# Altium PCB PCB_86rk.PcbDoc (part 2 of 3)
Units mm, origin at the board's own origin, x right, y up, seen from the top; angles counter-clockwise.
Board outline 185 x 150 mm, 2 copper layers (Top Layer, Bottom Layer); 95 components, 233 nets, 810 pads, 336 vias.
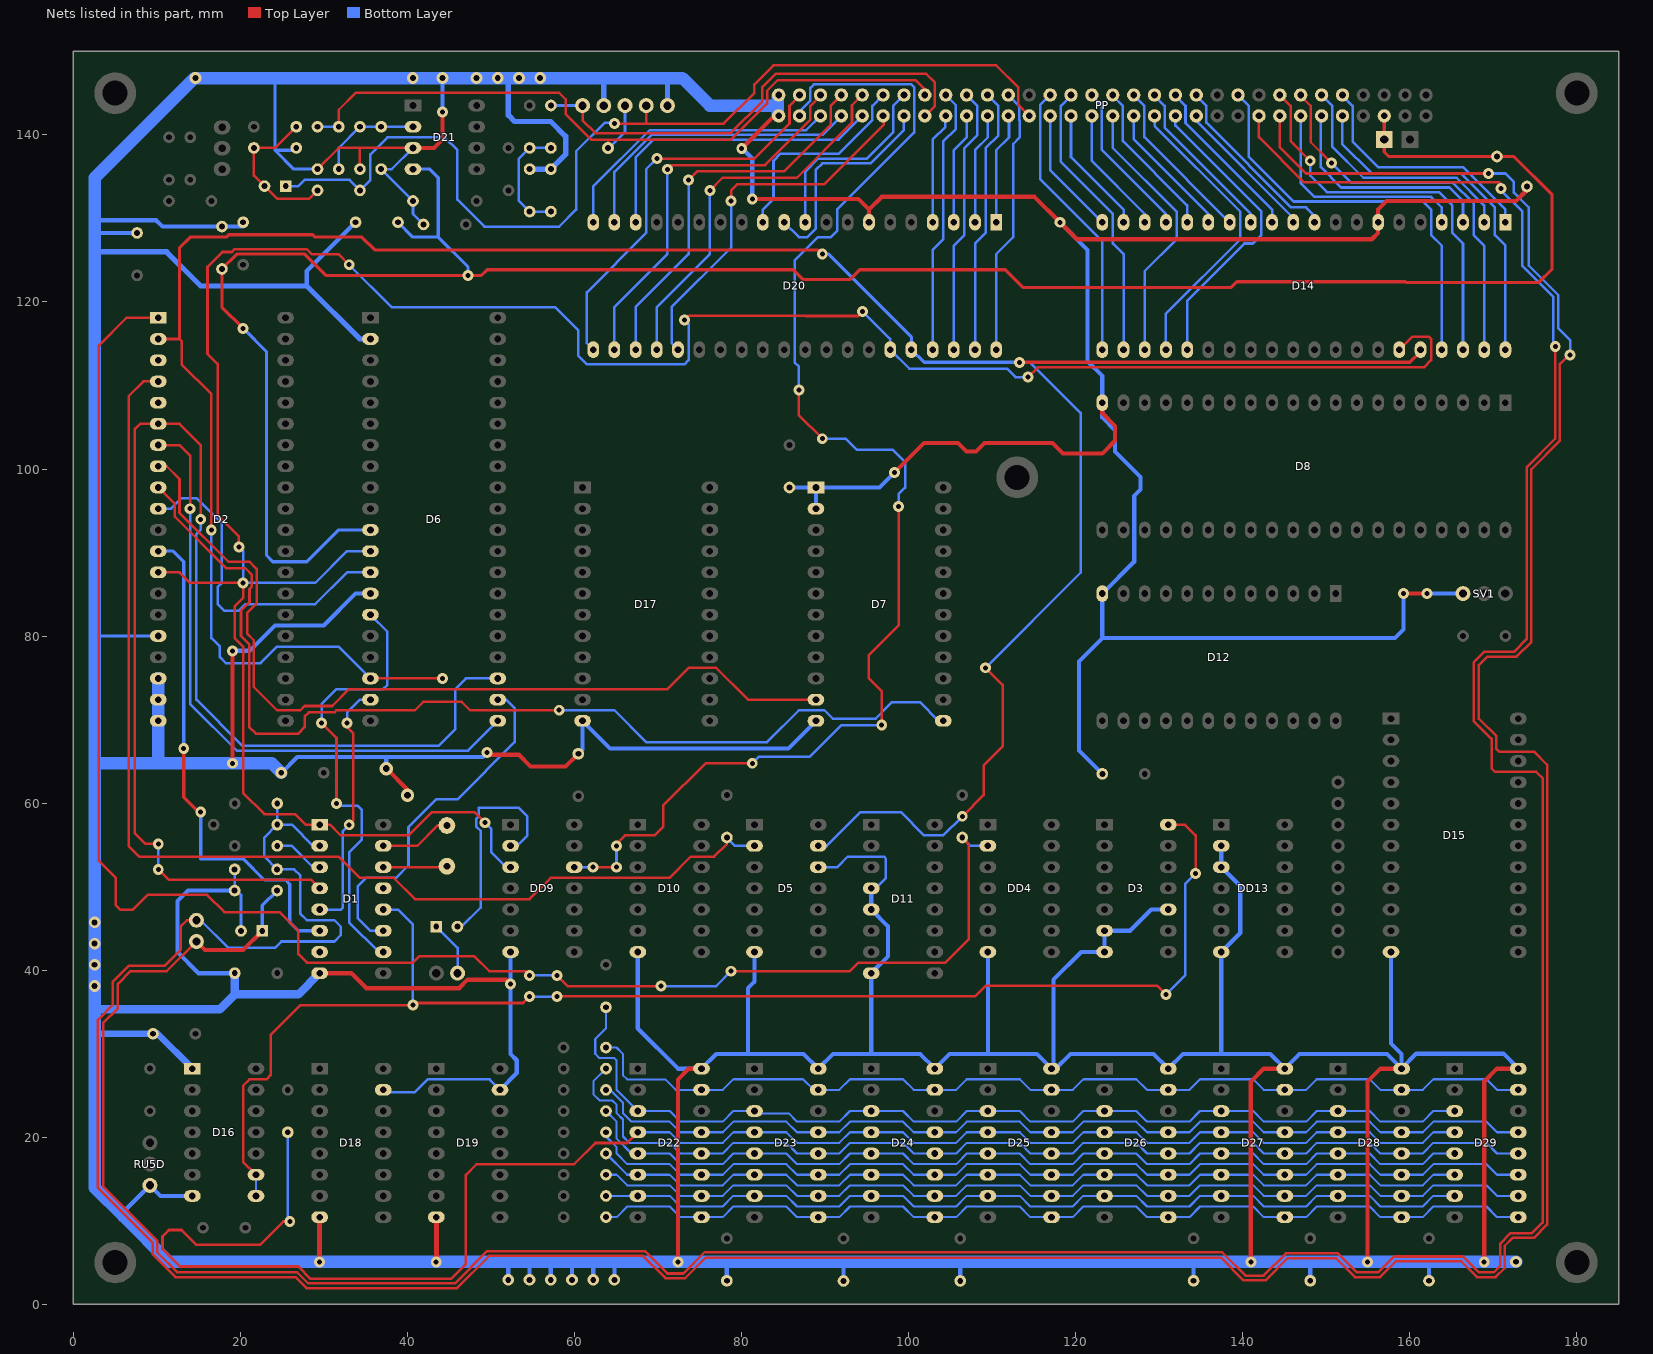
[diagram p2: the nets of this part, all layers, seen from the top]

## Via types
v1: diameter 1.3, hole 0.6, Top Layer to Bottom Layer, tented both sides, 301 vias
v2: diameter 1.4, hole 0.7, Top Layer to Bottom Layer, 27 vias
v3: diameter 1.4, hole 0.7, Top Layer to Bottom Layer, tented both sides, 4 vias
v4: diameter 3.2, hole 2.6, Top Layer to Bottom Layer, 2 vias
v5: diameter 1.6, hole 0.8, Top Layer to Bottom Layer, 1 vias
v6: diameter 1.6, hole 0.8, Top Layer to Bottom Layer, tented both sides, 1 vias

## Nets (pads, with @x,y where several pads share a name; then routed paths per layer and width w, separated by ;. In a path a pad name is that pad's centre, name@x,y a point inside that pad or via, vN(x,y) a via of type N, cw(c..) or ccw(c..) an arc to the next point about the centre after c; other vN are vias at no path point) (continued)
-5V: C9.1 C10.1 C14.1 D6.11 D21.4 pad.0@156.94,139.446 PP.Б30 | length 272.6
  Top Layer w0.381: v1(20.32,116.84) 17.78,119.38 C10.1@17.78,123.952 19.558,125.73 27.686,125.73 30.226,123.19 v1(47.244,123.19) 48.857,123.19 49.53,123.863 86.195,123.863 87.376,122.682 92.964,122.682 94.145,123.863 111.571,123.863 113.684,121.75 138.629,121.75 139.307,122.428 159.488,122.428 159.567,122.349 175.435,122.349 177.038,123.952 177.038,132.842 172.466,137.414 157.48,137.414 156.94,137.954 PP.Б30@156.94,142.28
  Bottom Layer w0.381: v1(20.32,116.84) 23.114,114.046 23.114,89.662 23.876,88.9 27.94,88.9 31.75,92.71 D6.11@35.56,92.71 ; C14.1@38.862,129.54 40.64,127.762 43.688,127.762 ; D21.4@40.656,135.906 42.656,135.906 43.688,134.874 43.688,127.762 ; v1(47.244,123.19) 47.244,124.206 43.688,127.762
B1: D22.5 D23.5 D24.5 D25.5 D26.5 D27.5 D28.5 D29.5 R21.1 | length 112.3
  Bottom Layer w0.254: R21.1@63.77,23.13 65.04,21.86 65.04,19.828 66.818,18.05 D22.5@67.58,18.05 71.39,18.05 72.66,16.78 77.74,16.78 79.01,18.05 D23.5@81.55,18.05 85.36,18.05 86.63,16.78 91.71,16.78 92.98,18.05 D24.5@95.52,18.05 99.33,18.05 100.6,16.78 105.68,16.78 106.95,18.05 D25.5@109.49,18.05 113.3,18.05 114.57,16.78 119.65,16.78 120.92,18.05 D26.5@123.46,18.05 127.27,18.05 128.54,16.78 133.62,16.78 134.89,18.05 D27.5@137.43,18.05 141.24,18.05 142.51,16.78 147.59,16.78 148.86,18.05 D28.5@151.4,18.05 155.21,18.05 156.48,16.78 161.56,16.78 162.83,18.05 D29.5@165.37,18.05
B2: D22.7 D23.7 D24.7 D25.7 D26.7 D27.7 D28.7 D29.7 R22.1 | length 109
  Bottom Layer w0.254: R22.1@63.77,12.97 D22.7@67.58,12.97 71.39,12.97 72.66,11.7 77.74,11.7 79.01,12.97 D23.7@81.55,12.97 85.36,12.97 86.63,11.7 91.71,11.7 92.98,12.97 D24.7@95.52,12.97 99.33,12.97 100.6,11.7 105.68,11.7 106.95,12.97 D25.7@109.49,12.97 113.3,12.97 114.57,11.7 119.65,11.7 120.92,12.97 D26.7@123.46,12.97 127.27,12.97 128.54,11.7 133.62,11.7 134.89,12.97 D27.7@137.43,12.97 141.24,12.97 142.51,11.7 147.59,11.7 148.86,12.97 D28.7@151.4,12.97 155.21,12.97 156.48,11.7 161.56,11.7 162.83,12.97 D29.7@165.37,12.97
B3: D22.6 D23.6 D24.6 D25.6 D26.6 D27.6 D28.6 D29.6 R23.1 | length 110
  Bottom Layer w0.254: R23.1@63.77,18.05 66.31,15.51 D22.6@67.58,15.51 71.39,15.51 72.66,14.24 77.74,14.24 79.01,15.51 D23.6@81.55,15.51 85.36,15.51 86.63,14.24 91.71,14.24 92.98,15.51 D24.6@95.52,15.51 99.33,15.51 100.6,14.24 105.68,14.24 106.95,15.51 D25.6@109.49,15.51 113.3,15.51 114.57,14.24 119.65,14.24 120.92,15.51 D26.6@123.46,15.51 127.27,15.51 128.54,14.24 133.62,14.24 134.89,15.51 D27.6@137.43,15.51 141.24,15.51 142.51,14.24 147.59,14.24 148.86,15.51 D28.6@151.4,15.51 155.21,15.51 156.48,14.24 161.56,14.24 162.83,15.51 D29.6@165.37,15.51
B4: D22.12 D23.12 D24.12 D25.12 D26.12 D27.12 D28.12 D29.12 R24.1 | length 126.5
  Bottom Layer w0.254: R24.1@63.77,28.21 62.246,26.686 62.246,25.162 63.008,24.4 64.532,24.4 65.04,23.892 65.04,22.876 65.802,22.114 65.802,20.082 66.564,19.32 71.39,19.32 72.66,18.05 D22.12@75.2,18.05 77.74,18.05 79.01,19.32 85.36,19.32 86.63,18.05 D23.12@89.17,18.05 91.71,18.05 92.98,19.32 99.33,19.32 100.6,18.05 D24.12@103.14,18.05 105.68,18.05 106.95,19.32 113.3,19.32 114.57,18.05 D25.12@117.11,18.05 119.65,18.05 120.92,19.32 127.27,19.32 128.54,18.05 D26.12@131.08,18.05 133.62,18.05 134.89,19.32 141.24,19.32 142.51,18.05 D27.12@145.05,18.05 147.59,18.05 148.86,19.32 155.21,19.32 156.48,18.05 D28.12@159.02,18.05 161.56,18.05 162.83,19.32 169.18,19.32 170.45,18.05 D29.12@172.99,18.05
B5: D22.11 D23.11 D24.11 D25.11 D26.11 D27.11 D28.11 D29.11 R25.1 | length 119.4
  Bottom Layer w0.254: R25.1@63.77,20.59 63.77,20.082 65.04,18.812 65.04,18.05 66.31,16.78 71.39,16.78 72.66,15.51 D22.11@75.2,15.51 77.74,15.51 79.01,16.78 85.36,16.78 86.63,15.51 D23.11@89.17,15.51 91.71,15.51 92.98,16.78 99.33,16.78 100.6,15.51 D24.11@103.14,15.51 105.68,15.51 106.95,16.78 113.3,16.78 114.57,15.51 D25.11@117.11,15.51 119.65,15.51 120.92,16.78 127.27,16.78 128.54,15.51 D26.11@131.08,15.51 133.62,15.51 134.89,16.78 141.24,16.78 142.51,15.51 D27.11@145.05,15.51 147.59,15.51 148.86,16.78 155.21,16.78 156.48,15.51 D28.11@159.02,15.51 161.56,15.51 162.83,16.78 169.18,16.78 170.45,15.51 D29.11@172.99,15.51
B6: D22.10 D23.10 D24.10 D25.10 D26.10 D27.10 D28.10 D29.10 R26.1 | length 117.6
  Bottom Layer w0.254: R26.1@63.77,15.51 65.04,15.51 66.31,14.24 71.39,14.24 72.66,12.97 D22.10@75.2,12.97 77.74,12.97 79.01,14.24 85.36,14.24 86.63,12.97 D23.10@89.17,12.97 91.71,12.97 92.98,14.24 99.33,14.24 100.6,12.97 D24.10@103.14,12.97 105.68,12.97 106.95,14.24 113.3,14.24 114.57,12.97 D25.10@117.11,12.97 119.65,12.97 120.92,14.24 127.27,14.24 128.54,12.97 D26.10@131.08,12.97 133.62,12.97 134.89,14.24 141.24,14.24 142.51,12.97 D27.10@145.05,12.97 147.59,12.97 148.86,14.24 155.21,14.24 156.48,12.97 D28.10@159.02,12.97 161.56,12.97 162.83,14.24 169.18,14.24 170.45,12.97 D29.10@172.99,12.97
B7: D22.13 D23.13 D24.13 D25.13 D26.13 D27.13 D28.13 D29.13 R27.1 | length 119.4
  Bottom Layer w0.254: R27.1@63.77,25.67 64.246,25.67 65.802,24.114 65.802,22.876 66.818,21.86 71.39,21.86 72.66,20.59 D22.13@75.2,20.59 77.74,20.59 79.01,21.86 85.36,21.86 86.63,20.59 D23.13@89.17,20.59 91.71,20.59 92.98,21.86 99.33,21.86 100.6,20.59 D24.13@103.14,20.59 105.68,20.59 106.95,21.86 113.3,21.86 114.57,20.59 D25.13@117.11,20.59 119.65,20.59 120.92,21.86 127.27,21.86 128.54,20.59 D26.13@131.08,20.59 133.62,20.59 134.89,21.86 141.24,21.86 142.51,20.59 D27.13@145.05,20.59 147.59,20.59 148.86,21.86 155.21,21.86 156.48,20.59 D28.13@159.02,20.59 161.56,20.59 162.83,21.86 169.18,21.86 170.45,20.59 D29.13@172.99,20.59
B8: D22.4 D23.4 D24.4 D25.4 D26.4 D27.4 D28.4 D29.4 R20.1 | length 206.8
  Top Layer w0.305: v1(25.908,9.906) 25.146,9.906 22.352,7.112 14.732,7.112 12.954,8.89 11.43,8.89 10.668,8.128 10.668,6.604 12.751,4.521 26.924,4.521 28.397,3.048 45.212,3.048 46.99,4.826 46.99,15.494 48.26,16.764 59.944,16.764 62.484,19.304 66.294,19.304 D22.4@67.58,20.59
  Bottom Layer w0.254: D22.4@67.58,20.59 71.39,20.59 72.66,19.32 77.74,19.32 79.01,20.59 D23.4@81.55,20.59 85.36,20.59 86.63,19.32 91.71,19.32 92.98,20.59 D24.4@95.52,20.59 99.33,20.59 100.6,19.32 105.68,19.32 106.95,20.59 D25.4@109.49,20.59 113.3,20.59 114.57,19.32 119.65,19.32 120.92,20.59 D26.4@123.46,20.59 127.27,20.59 128.54,19.32 133.62,19.32 134.89,20.59 D27.4@137.43,20.59 141.24,20.59 142.51,19.32 147.59,19.32 148.86,20.59 D28.4@151.4,20.59 155.21,20.59 156.48,19.32 161.56,19.32 162.83,20.59 D29.4@165.37,20.59
  Bottom Layer w0.305: R20.1@25.67,20.59 25.67,10.144 v1(25.908,9.906)
B9: D22.3 D23.3 D24.3 D25.3 D26.3 D27.3 D28.3 D29.3 R14.1 | length 121.3
  Bottom Layer w0.254: R14.1@63.754,35.56 63.754,33.02 62.484,31.75 62.484,29.972 62.992,29.464 64.77,29.464 65.024,29.21 65.024,25.686 D22.3@67.58,23.13 71.39,23.13 72.66,21.86 77.74,21.86 79.01,23.13 D23.3@81.55,23.13 81.82,22.86 85.63,22.86 86.63,21.86 91.71,21.86 92.98,23.13 D24.3@95.52,23.13 99.33,23.13 100.6,21.86 105.68,21.86 106.95,23.13 D25.3@109.49,23.13 113.3,23.13 114.57,21.86 119.65,21.86 120.92,23.13 D26.3@123.46,23.13 127.27,23.13 128.54,21.86 133.62,21.86 134.89,23.13 D27.3@137.43,23.13 141.24,23.13 142.51,21.86 147.59,21.86 148.86,23.13 D28.3@151.4,23.13 155.21,23.13 156.48,21.86 161.56,21.86 162.83,23.13 D29.3@165.37,23.13
B10: D22.15 D23.15 D24.15 D25.15 D26.15 D27.15 D28.15 D29.15 R28.1 | length 120.7
  Top Layer w0.305: D28.15@159.02,25.67 D28.15@159.528,25.67
  Bottom Layer w0.254: R28.1@63.754,30.734 65.024,30.734 65.786,29.972 65.786,27.432 66.294,26.924 70.866,26.924 72.12,25.67 D22.15@75.2,25.67 77.74,25.67 79.01,26.94 87.36,26.94 88.63,25.67 D23.15@89.17,25.67 91.71,25.67 92.98,26.94 99.33,26.94 100.6,25.67 D24.15@103.14,25.67 105.68,25.67 106.95,26.94 113.3,26.94 114.57,25.67 D25.15@117.11,25.67 119.65,25.67 120.92,26.94 127.27,26.94 128.54,25.67 D26.15@131.08,25.67 133.62,25.67 134.89,26.94 141.24,26.94 142.51,25.67 D27.15@145.05,25.67 147.59,25.67 148.86,26.94 155.21,26.94 156.48,25.67 D28.15@159.02,25.67 161.56,25.67 162.83,26.94 169.18,26.94 170.45,25.67 D29.15@172.99,25.67
B11: D22.9 D23.9 D24.9 D25.9 D26.9 D27.9 D28.9 D29.9 R34.1 | length 117.6
  Bottom Layer w0.254: R34.1@63.77,10.43 65.04,10.43 66.31,11.7 71.39,11.7 72.66,10.43 D22.9@75.2,10.43 77.74,10.43 79.01,11.7 85.36,11.7 86.63,10.43 D23.9@89.17,10.43 91.71,10.43 92.98,11.7 99.33,11.7 100.6,10.43 D24.9@103.14,10.43 105.68,10.43 106.95,11.7 113.3,11.7 114.57,10.43 D25.9@117.11,10.43 119.65,10.43 120.92,11.7 127.27,11.7 128.54,10.43 D26.9@131.08,10.43 133.62,10.43 134.89,11.7 141.24,11.7 142.51,10.43 D27.9@145.05,10.43 147.59,10.43 148.86,11.7 155.21,11.7 156.48,10.43 D28.9@159.02,10.43 161.56,10.43 162.83,11.7 169.18,11.7 170.45,10.43 D29.9@172.99,10.43
C1: D14.4 PP.Б26 | length 27.9
  Bottom Layer w0.305: PP.Б26@146.94,142.28 146.94,134.238 148.59,132.588 162.56,132.588 163.83,131.318 D14.4@163.83,129.54
C2: D14.3 PP.Б27 | length 27.4
  Bottom Layer w0.305: PP.Б27@149.44,142.28 149.352,142.192 149.352,136.144 151.79,133.706 164.744,133.706 166.37,132.08 D14.3@166.37,129.54
C3: D14.2 PP.А27 | length 29.9
  Bottom Layer w0.305: PP.А27@149.44,144.78 150.734,143.486 150.734,138.572 154.432,134.874 165.608,134.874 168.91,131.572 D14.2@168.91,129.54
C4: D14.1 PP.А28 | length 29.3
  Bottom Layer w0.305: PP.А28@151.94,144.78 151.94,144.693 153.146,143.486 153.146,139.208 156.21,136.144 166.37,136.144 171.45,131.064 D14.1@171.45,129.54
C5: D14.40 PP.Б28 | length 42.4
  Bottom Layer w0.305: PP.Б28@151.94,142.28 151.892,142.232 151.892,138.938 155.397,135.433 166.065,135.433 170.18,131.318 170.18,128.016 171.45,126.746 D14.40@171.45,114.3
C6: D14.39 PP.А26 | length 46.7
  Top Layer w0.305: PP.А26@146.94,144.78 146.94,144.693 148.146,143.486 148.146,139.128 v1(150.622,136.652)
  Bottom Layer w0.305: v1(150.622,136.652) 153.01,134.264 165.202,134.264 167.64,131.826 167.64,128.016 168.91,126.746 D14.39@168.91,114.3
C7: D14.38 PP.А25 | length 47.4
  Top Layer w0.305: PP.А25@144.44,144.78 145.734,143.486 145.734,139.254 v1(148.082,136.906)
  Bottom Layer w0.305: v1(148.082,136.906) 148.082,135.128 150.063,133.147 163.525,133.147 165.1,131.572 165.1,128.27 166.37,127 D14.38@166.37,114.3
C8: D14.37 PP.А23 | length 49.7
  Bottom Layer w0.305: PP.А23@139.44,144.78 140.716,143.504 140.716,137.414 146.101,132.029 161.595,132.029 162.56,131.064 162.56,128.016 163.83,126.746 D14.37@163.83,114.3
C9: D14.18 PP.Б16 | length 15.4
  Bottom Layer w0.305: PP.Б16@121.94,142.28 121.94,136.886 128.27,130.556 D14.18@128.27,129.54
C10: D14.19 PP.Б15 | length 15.3
  Bottom Layer w0.305: PP.Б15@119.44,142.28 119.44,137.354 125.73,131.064 D14.19@125.73,129.54
C11: D14.20 PP.Б14 | length 15.3
  Bottom Layer w0.305: PP.Б14@116.94,142.28 116.94,135.79 D14.20@123.19,129.54
C12: D14.21 PP.А14 | length 34.1
  Bottom Layer w0.305: PP.А14@116.94,144.78 115.734,143.574 115.734,134.71 123.19,127.254 D14.21@123.19,114.3
C13: D14.22 PP.А15 | length 34.1
  Bottom Layer w0.305: PP.А15@119.44,144.78 119.44,144.693 118.234,143.486 118.234,136.782 124.46,130.556 124.46,127 125.73,125.73 D14.22@125.73,114.3
C14: D14.23 PP.Б17 | length 32.7
  Bottom Layer w0.305: PP.Б17@124.44,142.28 124.44,138.45 132.08,130.81 132.08,127.508 128.27,123.698 D14.23@128.27,114.3
C15: D14.24 PP.Б19 | length 35.9
  Bottom Layer w0.305: PP.Б19@129.44,142.28 129.44,141.07 139.7,130.81 139.7,127.508 130.81,118.618 D14.24@130.81,114.3
C16: D14.25 PP.Б20 | length 36.5
  Bottom Layer w0.305: PP.Б20@131.94,142.28 131.94,141.11 142.24,130.81 142.24,128.016 141.224,127 140.208,127 133.35,120.142 D14.25@133.35,114.3
C17: D14.14 PP.А18 | length 20
  Bottom Layer w0.305: PP.А18@126.94,144.78 128.234,143.486 128.234,139.736 D14.14@138.43,129.54
C18: D14.15 PP.Б18 | length 16.4
  Bottom Layer w0.305: PP.Б18@126.94,142.28 126.94,139.506 135.89,130.556 D14.15@135.89,129.54
C19: D14.16 PP.А17 | length 18.9
  Bottom Layer w0.305: PP.А17@124.44,144.78 124.44,144.693 125.646,143.486 125.646,139.276 133.35,131.572 D14.16@133.35,129.54
C20: D14.17 PP.А16 | length 18.9
  Bottom Layer w0.305: PP.А16@121.94,144.78 121.94,144.693 123.146,143.486 123.146,138.22 130.81,130.556 D14.17@130.81,129.54
C21: D14.13 PP.А19 | length 20
  Bottom Layer w0.305: PP.А19@129.44,144.78 129.44,144.693 130.646,143.486 130.646,140.88 140.97,130.556 D14.13@140.97,129.54
C22: D14.12 PP.А20 | length 20
  Bottom Layer w0.305: PP.А20@131.94,144.78 131.94,144.693 133.146,143.486 133.146,141.428 143.51,131.064 D14.12@143.51,129.54
C23: D14.11 PP.Б21 | length 17.5
  Bottom Layer w0.305: PP.Б21@134.44,142.28 134.44,141.658 146.05,130.048 D14.11@146.05,129.54
C24: D14.10 PP.А21 | length 22.1
  Bottom Layer w0.305: PP.А21@134.44,144.78 134.44,144.693 135.646,143.486 135.646,141.468 145.796,131.318 147.574,131.318 148.59,130.302 D14.10@148.59,129.54
C25: C3.1 C4.1 pad.3 PP.Б13 | length 120.9
  Top Layer w0.305: v1(64.77,141.351) 68.58,141.351 ; pad.3@68.58,143.51 68.58,141.351 ; PP.Б13@114.44,142.28 113.146,143.574 113.146,145.68 110.49,148.336 83.82,148.336 81.534,146.05 81.534,145.034 77.851,141.351 68.58,141.351
  Bottom Layer w0.305: C3.1@25.416,133.874 26.94,133.874 27.686,134.62 33.052,134.62 C4.1@34.306,133.366 35.56,134.62 35.56,137.668 37.592,139.7 44.45,139.7 45.974,138.176 45.974,132.251 49.193,129.032 58.166,129.032 60.198,131.064 60.198,138.049 63.627,141.478 v1@64.897,141.478
C26: C5.2 pad.2 PP.А8 R29.2 | length 90.9
  Top Layer w0.305: C5.2@31.766,140.986 31.766,143.018 33.782,145.034 58.166,145.034 58.928,144.272 58.928,142.494 61.976,139.446 64.008,139.446 ; v3(64.008,138.43) 64.008,139.446 ; PP.А8@101.94,144.78 101.94,145.456 100.838,146.558 84.328,146.558 83.058,145.288 83.058,143.764 78.74,139.446 64.008,139.446
  Bottom Layer w0.305: R29.2@29.226,140.986 C5.2@31.766,140.986 ; v3(64.008,138.43) 64.135,138.43 66.04,140.335 pad.2@66.04,143.51
C27: D20.10 PP.А7 | length 23.6
  Bottom Layer w0.305: D20.10@87.63,129.54 87.63,135.636 89.154,137.16 94.996,137.16 98.146,140.31 98.146,143.486 PP.А7@99.44,144.78
C28: D20.11 PP.Б7 | length 26.2
  Bottom Layer w0.305: D20.11@85.09,129.54 86.868,127.762 87.884,127.762 88.9,128.778 88.9,135.839 89.662,136.601 95.453,136.601 99.441,140.589 99.44,140.59 PP.Б7@99.44,142.28
C29: D20.12 PP.А6 | length 25.3
  Bottom Layer w0.305: D20.12@82.55,129.54 82.55,131.064 83.82,132.334 83.82,136.906 84.684,137.77 91.636,137.77 95.646,141.78 95.646,143.486 PP.А6@96.94,144.78
C30: D20.25 PP.Б6 | length 45
  Top Layer w0.305: v1(78.74,132.08) 78.74,133.35 79.502,134.112 89.916,134.112 97.028,141.224 97.028,142.192 PP.Б6@96.94,142.28
  Bottom Layer w0.305: D20.25@72.39,114.3 71.628,115.062 71.628,119.38 78.74,126.492 v1(78.74,132.08)
C31: D20.24 PP.А5 | length 45.9
  Top Layer w0.305: v1(76.2,133.35) 77.724,134.874 86.614,134.874 93.218,141.478 93.218,143.558 PP.А5@94.44,144.78
  Bottom Layer w0.305: D20.24@69.85,114.3 69.85,119.38 76.2,125.73 v1(76.2,133.35)
C32: D20.23 PP.А4 | length 46.8
  Top Layer w0.305: v1(73.66,134.62) 74.676,135.636 85.09,135.636 90.678,141.224 90.678,143.518 PP.А4@91.94,144.78
  Bottom Layer w0.305: D20.23@67.31,114.3 67.31,119.38 73.66,125.73 v1(73.66,134.62)
C33: D20.22 PP.А3 | length 47.2
  Top Layer w0.305: v1(71.12,135.89) 71.628,136.398 82.804,136.398 88.234,141.828 88.234,143.486 89.44,144.693 PP.А3@89.44,144.78
  Bottom Layer w0.305: D20.22@64.77,114.3 64.77,119.38 71.12,125.73 v1(71.12,135.89)
C34: D20.21 PP.А2 | length 48.2
  Top Layer w0.305: v1(69.85,137.16) 81.534,137.16 85.734,141.36 85.734,143.486 86.94,144.693 PP.А2@86.94,144.78
  Bottom Layer w0.305: D20.21@62.23,114.3 61.468,115.062 61.468,121.158 68.58,128.27 68.58,135.89 v1(69.85,137.16)
C35: D20.20 PP.Б3 | length 35
  Bottom Layer w0.305: D20.20@62.23,129.54 62.23,133.813 68.981,140.564 87.724,140.564 PP.Б3@89.44,142.28
C36: D20.19 PP.Б4 | length 36
  Bottom Layer w0.305: D20.19@64.77,129.54 64.77,135.563 69.212,140.005 89.665,140.005 PP.Б4@91.94,142.28
C37: D20.18 PP.Б5 | length 37
  Bottom Layer w0.305: D20.18@67.31,129.54 67.31,137.312 69.444,139.446 91.606,139.446 PP.Б5@94.44,142.28
C38: D20.37 PP.А9 | length 32.1
  Bottom Layer w0.305: D20.37@102.87,114.3 102.87,126.238 104.14,127.508 104.14,139.192 105.664,140.716 105.664,143.556 PP.А9@104.44,144.78
C39: D20.38 PP.А10 | length 32.2
  Bottom Layer w0.305: D20.38@105.41,114.3 105.41,126.746 106.68,128.016 106.68,138.43 108.204,139.954 108.204,143.516 PP.А10@106.94,144.78
C40: D20.39 PP.А11 | length 32.2
  Bottom Layer w0.305: D20.39@107.95,114.3 107.95,127 109.22,128.27 109.22,138.43 110.744,139.954 110.744,141.77 110.734,141.78 110.734,143.486 PP.А11@109.44,144.78
C41: D20.40 PP.А12 | length 32.2
  Bottom Layer w0.305: D20.40@110.49,114.3 110.49,125.73 112.522,127.762 112.522,138.938 113.284,139.7 113.284,141.73 113.234,141.78 113.234,143.486 PP.А12@111.94,144.78
C42: D20.1 PP.Б12 | length 13.4
  Bottom Layer w0.305: D20.1@110.49,129.54 110.49,138.176 112.014,139.7 112.014,142.206 PP.Б12@111.94,142.28
C43: D20.2 PP.Б11 | length 13.4
  Bottom Layer w0.305: D20.2@107.95,129.54 107.95,138.176 109.474,139.7 109.474,142.246 PP.Б11@109.44,142.28
C44: D20.3 PP.Б10 | length 13.4
  Bottom Layer w0.305: D20.3@105.41,129.54 105.41,138.176 106.934,139.7 106.934,142.274 PP.Б10@106.94,142.28
C45: D20.4 PP.Б9 | length 13.4
  Bottom Layer w0.305: D20.4@102.87,129.54 102.87,139.446 104.394,140.97 104.394,142.234 PP.Б9@104.44,142.28
C46: C8.2 pad.0@60.96,143.51 PP.Б8 | length 57.3
  Top Layer w0.305: pad.0@60.96,143.51 60.96,141.732 62.484,140.208 78.689,140.208 82.499,144.018 82.499,145.745 84.074,147.32 102.108,147.32 103.146,146.282 103.146,143.486 PP.Б8@101.94,142.28
  Bottom Layer w0.305: C8.2@57.166,143.526 60.944,143.526 pad.0@60.96,143.51
C47: DD9.12 PP.Б2 | length 159
  Top Layer w0.305: v1(62.23,52.324) v1(65.024,52.324) ; v1@64.897,54.991 66.04,56.134 69.596,56.134 70.612,57.15 70.612,59.69 75.692,64.77 v1(81.28,64.77) ; v1(86.868,109.474) 86.868,106.426 v1(89.662,103.632) ; v1(96.774,69.342) 96.774,73.406 95.25,74.93 95.25,77.724 98.806,81.28 v1(98.806,95.504)
  Bottom Layer w0.305: DD9.12@59.96,52.34 62.214,52.34 v1(62.23,52.324) ; v1(65.024,52.324) v1(65.024,54.864) v1@65.024,55.118 ; v1(81.28,64.77) 82.042,65.532 88.138,65.532 91.948,69.342 v1(96.774,69.342) ; v1(86.868,109.474) 86.868,112.268 86.36,112.776 86.36,124.968 89.154,127.762 90.678,127.762 91.44,128.524 91.44,131.064 100.646,140.27 100.646,145.734 100.33,146.05 88.646,146.05 88.234,145.638 88.234,144.114 86.94,142.82 PP.Б2@86.94,142.28 ; v1(89.662,103.632) 92.456,103.632 93.766,102.322 98.084,102.322 99.568,100.838 99.568,97.79 98.806,97.028 v1(98.806,95.504)
GND: C1.2 C2.1 C6.2 C7.2 C9.2 C10.2 C11.2 C12.2 C13.2 C14.2 C17.2 C18.2 C19.2 C20.2 C21.2 C22.2 C23.2 C24.2 C25.2 C50.2 C51.2 C52.1 D1.8 D2.16 D2.18 D2.19 D2.20 D3.6 D3.7 D3.10 D5.7 D5.12 D6.2 D6.14 D7.1 D7.2 D7.12 D8.20 D10.7 D11.4 D11.5 D11.8 D12.12 D14.7 D15.12 D16.1 D16.7 D17.12 D18.8 D18.15 D19.8 D19.15 D20.7 D21.3 D22.16 D23.16 D24.16 D25.16 D26.16 D27.16 D28.16 D29.16 DD4.7 DD9.7 DD13.2 DD13.3 DD13.7 pad.1@63.5,143.51 pad.4 PP.А1 PP.Б1 R2.1 R19.1 R29.1 R30.1 R33.2 RU5D.3 SV1.1 V3.A | length 1522.6
  Top Layer w0.305: R29.1@29.226,135.906 31.766,138.446 34.29,138.446 ; R30.1@34.306,135.906 34.306,138.43 34.29,138.446 ; D21.3@40.656,138.446 34.29,138.446
  Top Layer w0.508: v1(19.05,64.77) v1(19.05,78.232) ; D1.8@29.48,39.64 33.258,39.64 35.052,37.846 46.187,37.846 47.203,38.862 51.816,38.862 v1(52.324,38.354) ; v6(37.465,64.135) 40.005,61.595 v5(40.005,60.96) ; D21.3@40.656,138.446 43.164,138.446 43.18,138.43 44.196,139.446 v1(44.196,142.748) ; v1(49.53,66.04) 49.784,65.786 53.34,65.786 54.737,64.389 58.928,64.389 C52.1@60.452,65.913 ; v1(72.39,5.08) 72.39,26.924 73.676,28.21 D22.16@75.2,28.21 ; v1(80.01,138.39) 83.9,142.28 PP.Б1@84.44,142.28 ; v1(81.28,132.334) 93.98,132.334 95.25,131.064 ; D20.7@95.25,129.54 95.25,131.064 ; v1(98.298,99.568) 101.854,103.124 105.918,103.124 106.934,102.108 108.077,102.108 109.093,103.124 117.221,103.124 118.491,101.854 123.19,101.854 124.714,103.378 124.714,105.156 123.19,106.68 D8.20@123.19,107.95 ; v1(140.97,5.08) 140.97,26.67 142.51,28.21 D27.16@145.05,28.21 ; v1(154.94,5.08) 154.94,26.67 156.48,28.21 D28.16@159.02,28.21 ; v1(159.258,85.09) v1(162.052,85.09) ; v1(168.91,5.08) 168.91,26.67 170.45,28.21 D29.16@172.99,28.21 ; C9.2@173.954,133.822 173.954,133.314 172.72,132.08 157.226,132.08 156.21,131.064 D14.7@156.21,129.54 156.21,128.27 155.448,127.508 120.142,127.508 v1(118.11,129.54) 115.062,132.588 96.774,132.588 95.25,131.064
  Top Layer w0.6: v1(29.464,5.08) 29.48,5.096 D18.8@29.48,10.43 ; v1(43.434,5.08) 43.45,5.096 D19.8@43.45,10.43
  Bottom Layer w0.305: 2.54,128.524 2.794,128.27 ; C2.1@19.304,52.324 C2.1@19.304,52.07 19.304,49.784 20.066,49.022 C1.2@20.066,44.704 ; D18.15@37.1,25.67 37.37,25.4 40.894,25.4 42.418,26.924 49.816,26.924 D19.15@51.07,25.67 ; D21.3@40.656,138.446 38.116,135.906 C6.2@36.846,135.906 V3.A@40.656,132.096 40.656,130.54 C13.2@41.91,129.286 ; D5.12@89.17,52.34 91.456,52.34 92.71,53.594 97.028,53.594 97.282,53.34 97.282,51.054 96.028,49.8 D11.4@95.52,49.8
  Bottom Layer w0.381: 2.54,80.264 2.794,80.01 D2.16@10.16,80.01 ; 24.384,146.812 24.13,146.558 24.13,138.176 ; R19.1@26.686,138.446 26.416,138.176 24.13,138.176 ; R29.1@29.226,135.906 26.4,135.906 24.13,138.176
  Bottom Layer w0.508: 2.794,128.27 C12.2@7.62,128.27 ; 2.794,129.794 9.906,129.794 10.668,129.032 C10.2@17.78,129.032 C25.2@20.32,129.032 ; 5.969,10.541 5.969,11.049 RU5D.3@9.16,14.24 10.43,12.97 D16.7@14.24,12.97 ; v1(19.05,78.232) 21.082,78.232 24.13,81.28 29.972,81.28 33.782,85.09 D6.14@35.56,85.09 ; R2.1@19.304,49.53 13.716,49.53 12.446,48.26 12.446,42.164 14.986,39.624 15.002,39.64 C11.2@19.32,39.64 ; C51.2@24.892,63.627 26.797,65.532 37.465,65.532 ; 27.94,121.92 27.94,123.698 C14.2@33.782,129.54 ; v6(37.465,64.135) 37.465,65.532 ; v2@43.688,146.812 44.196,146.304 v1(44.196,142.748) ; v1(49.53,66.04) 49.022,65.532 37.465,65.532 ; D19.15@51.07,25.67 53.086,27.686 53.086,29.21 52.332,29.964 52.332,33.544 52.34,33.552 DD9.7@52.34,42.18 ; v2@52.07,2.54 v2(52.07,2.921) 52.07,5.08 ; v2@54.61,2.54 v2(54.61,2.921) 54.61,5.08 ; v2@57.15,2.54 v2(57.15,2.921) 57.15,5.08 ; v2@59.69,2.54 v2(59.69,2.921) 59.69,5.08 ; C52.1@60.261,65.722 C52.1@60.452,65.913 60.96,66.421 D17.12@60.96,69.85 64.262,66.548 85.598,66.548 D7.12@88.9,69.85 ; v2@62.23,2.54 v2(62.23,2.921) 62.23,5.08 ; v2@64.77,2.54 v2(64.77,2.921) 64.77,5.08 ; D10.7@67.58,42.18 67.58,38.878 67.564,38.862 67.564,33.036 72.39,28.21 D22.16@75.2,28.21 76.962,29.972 80.772,29.972 ; C22.2@78.232,2.794 C22.2@78.232,2.81 78.232,5.08 ; v1(80.01,138.39) 80.01,138.43 81.28,137.16 v1(81.28,132.334) ; D5.7@81.55,42.18 81.55,38.624 80.772,37.846 80.772,29.972 ; C50.2@85.725,97.79 D7.1@88.9,97.79 ; D7.2@88.9,95.25 D7.1@88.9,97.79 ; C21.2@92.202,2.794 92.202,5.064 ; D11.4@95.52,49.8 D11.5@95.52,47.26 97.536,45.244 97.536,41.656 D11.8@95.52,39.64 95.52,29.972 ; v1(98.298,99.568) 96.52,97.79 D7.1@88.9,97.79 ; C20.2@106.172,2.794 106.172,5.064 ; DD4.7@109.49,42.18 109.49,29.972 ; v1(118.11,129.54) 121.412,126.238 121.412,112.903 123.19,111.125 D8.20@123.19,107.95 123.19,106.172 124.714,104.648 124.714,102.108 127.762,99.06 127.762,97.536 127,96.774 127,88.9 D12.12@123.19,85.09 123.19,79.756 ; C24.2@123.19,63.5 120.396,66.294 120.396,76.962 123.19,79.756 ; D3.10@131.08,47.26 129.048,47.26 126.508,44.72 D3.6@123.46,44.72 D3.7@123.46,42.18 120.666,42.18 117.348,38.862 117.348,28.448 D25.16@117.11,28.21 ; C19.2@134.112,2.81 134.112,5.08 ; DD13.2@137.43,54.88 DD13.3@137.43,52.34 139.7,50.07 139.7,44.45 DD13.7@137.43,42.18 137.43,29.972 ; C18.2@148.082,2.81 148.082,5.08 ; D15.12@157.75,42.18 157.75,31.226 159.02,29.956 D28.16@159.02,28.242 ; D28.16@159.02,28.21 D28.16@159.02,28.242 ; v1(159.258,85.09) 159.258,80.772 158.242,79.756 123.19,79.756 ; v1(162.052,85.09) SV1.1@166.37,85.09 ; C17.2@162.306,2.81 162.306,5.08 ; D29.16@172.99,28.242 171.228,30.004 160.782,30.004 D28.16@159.02,28.242 ; 80.772,29.972 87.408,29.972 D23.16@89.17,28.21 90.932,29.972 95.52,29.972 ; 95.52,29.972 101.378,29.972 D24.16@103.14,28.21 104.902,29.972 109.49,29.972 ; 109.49,29.972 115.348,29.972 D25.16@117.11,28.21 ; D25.16@117.11,28.21 117.618,28.21 119.38,29.972 129.318,29.972 D26.16@131.08,28.21 132.842,29.972 137.43,29.972 ; 137.43,29.972 143.288,29.972 D27.16@145.05,28.21 146.812,29.972 157.258,29.972 159.004,28.226 D28.16@159.02,28.242
  Bottom Layer w0.6: 2.54,29.718 2.794,29.972
  Bottom Layer w0.635: 2.54,126 11.16,126 15.24,121.92 27.94,121.92 34.29,115.57 D6.2@35.56,115.57 ; 52.197,146.812 52.07,146.685 52.07,142.367 52.832,141.605 57.15,141.605 58.928,139.827 58.928,137.668 C7.2@57.166,135.906 R33.2@54.626,135.906 ; pad.1@63.5,143.51 63.5,146.812 ; pad.4@71.12,143.51 71.12,146.685 71.247,146.812
  Bottom Layer w0.8: 2.54,32.258 2.667,32.385 C23.2@9.525,32.385 10.065,32.385 D16.1@14.24,28.21
  Bottom Layer w1.016: 2.54,35.306 17.526,35.306 19.32,37.1 ; C11.2@19.32,39.64 19.32,37.1 ; D1.8@29.48,39.64 26.94,37.1 19.32,37.1
  Bottom Layer w1.5: D2.18@10.16,74.93 D2.19@10.16,72.39 D2.20@10.16,69.85 10.16,64.77 ; C51.2@24.892,63.627 23.749,64.77 v1(19.05,64.77) 10.16,64.77 ; PP.Б1@84.44,142.28 84.328,142.392 84.328,143.51 ; PP.А1@84.44,144.78 84.328,144.668 84.328,143.51 ; v2(172.72,5.08) v1(168.91,5.08) 162.306,5.08 v1(154.94,5.08) 148.082,5.08 v1(140.97,5.08) 134.112,5.08 120.142,5.08 106.172,5.08 78.232,5.08 v1(72.39,5.08) 64.77,5.08 62.23,5.08 59.69,5.08 57.15,5.08 54.61,5.08 52.07,5.08 v1(43.434,5.08) v1(29.464,5.08) 11.43,5.08 5.969,10.541 2.54,13.97 2.54,29.718 2.54,32.258 2.54,35.306 v2(2.54,38.1) v2(2.54,40.64) v2(2.54,43.18) v2(2.54,45.72) 2.54,64.77 ; 2.54,64.77 10.16,64.77 ; 2.54,64.77 2.54,80.264 2.54,126 2.54,128.524 2.54,134.874 14.478,146.812 v2(14.605,146.812) 24.384,146.812 v2(40.64,146.812) 43.688,146.812 v2(44.196,146.812) v2(48.26,146.812) v2(50.8,146.812) 52.197,146.812 v2(53.34,146.812) v2(55.88,146.812) 63.5,146.812 71.247,146.812 72.898,146.812 76.2,143.51 84.328,143.51
NetC1_1: C1.1 PP.Б24 R2.2 RESET.1 | length 415.4
  Top Layer w0.305: RESET.1@14.732,43.434 11.176,39.878 6.858,39.878 5.334,38.354 5.334,35.433 3.556,33.655 3.556,14.097 10.033,7.62 10.033,6.223 12.446,3.81 26.797,3.81 28.118,2.489 45.669,2.489 49.53,6.35 68.453,6.35 71.12,3.683 73.025,3.683 75.565,6.223 137.541,6.223 140.335,3.429 142.494,3.429 145.161,6.096 151.384,6.096 153.67,3.81 156.21,3.81 158.115,5.715 166.37,5.715 168.275,3.81 170.053,3.81 170.815,4.572 170.815,7.239 172.085,8.509 174.625,8.509 175.895,9.779 175.895,62.992 175.133,63.754 170.18,63.754 169.799,64.135 169.799,67.691 167.64,69.85 167.64,76.835 168.91,78.105 172.466,78.105 173.99,79.629 173.99,100.203 177.419,103.632 v1(177.419,114.681) ; PP.Б24@141.94,142.28 141.94,139.746 147.36,134.326 170.728,134.326 v1@171.45,133.604
  Top Layer w0.508: RESET.1@14.732,43.434 15.748,42.418 20.32,42.418 C1.1@22.606,44.704
  Bottom Layer w0.305: v1(170.942,133.604) 170.942,133.35 173.482,130.81 173.482,124.333 177.165,120.65 177.165,114.935 v1(177.419,114.681)
  Bottom Layer w0.381: C1.1@22.606,44.704 22.606,47.752 R2.2@24.384,49.53
NetC2_2: C2.2 D1.2 PP.Б25 R1.1 RESET.2 V1.A | length 453.7
  Top Layer w0.305: RESET.2@14.732,45.974 13.589,45.974 12.827,45.212 12.827,42.418 10.922,40.513 6.604,40.513 4.699,38.608 4.699,35.814 2.921,34.036 2.921,13.942 9.474,7.389 9.474,5.992 12.215,3.251 26.566,3.251 27.886,1.93 45.923,1.93 49.784,5.791 68.222,5.791 70.889,3.124 73.256,3.124 75.706,5.574 137.4,5.574 140.104,2.87 142.725,2.87 145.366,5.51 151.179,5.51 153.439,3.251 156.441,3.251 158.32,5.129 166.165,5.129 168.044,3.251 170.284,3.251 171.374,4.341 171.374,7.008 172.316,7.95 174.856,7.95 176.454,9.548 176.454,64.592 174.879,66.167 170.688,66.167 170.358,66.497 170.358,68.021 168.275,70.104 168.275,76.53 169.291,77.546 172.796,77.546 174.549,79.299 174.549,99.972 177.978,103.401 177.978,112.573 v1@179.07,113.665 ; PP.Б25@144.44,142.28 144.44,138.516 147.574,135.382 v1(169.418,135.382)
  Bottom Layer w0.305: RESET.2@15.24,45.974 18.542,42.672 24.13,42.672 24.892,43.434 31.242,43.434 32.004,44.196 32.004,45.212 31.242,45.974 27.94,45.974 27.178,46.736 27.178,51.308 26.416,52.07 C2.2@24.384,52.07 22.86,53.594 22.86,55.88 V1.A@24.4,57.42 ; R1.1@24.4,59.96 V1.A@24.4,57.42 ; D1.2@29.48,54.88 28.686,54.88 26.146,57.42 V1.A@24.4,57.42 ; v1(169.418,135.382) 171.45,135.382 172.466,134.366 172.466,133.096 174.244,131.318 174.244,124.361 177.8,120.805 177.8,116.84 179.197,115.443 v1(179.197,113.665)
NetC3_2: C3.2 C4.2 R18.1 R19.2 | length 18.6
  Top Layer w0.305: R18.1@26.686,140.986 24.146,138.446 R19.2@21.606,138.446 21.606,135.144 C3.2@22.876,133.874 24.416,132.334 28.194,132.334 C4.2@29.226,133.366
NetC5_1: C5.1 C6.1 D21.2 R30.2 | length 12.5
  Bottom Layer w0.305: C5.1@31.766,135.906 31.766,138.446 R30.2@34.306,140.986 C6.1@36.846,140.986 D21.2@40.656,140.986
NetC7_1: C7.1 C8.1 R32.1 R33.1 | length 13.8
  Bottom Layer w0.305: C7.1@57.166,130.826 R33.1@54.626,130.826 53.34,132.112 53.34,137.16 R32.1@54.626,138.446 C8.1@57.166,138.446
NetC26_1: C26.1 H1.1 | length 6.6
  Bottom Layer w0.305: C26.1@43.434,45.212 45.99,42.656 H1.1@45.99,39.64
NetC26_2: C26.2 DD9.2 | length 27.1
  Bottom Layer w0.305: C26.2@45.974,45.212 46.482,45.212 48.768,47.498 48.768,56.672 48.22,57.22 48.22,58.096 48.514,58.39 48.514,59.436 53.34,59.436 54.356,58.42 54.356,56.134 53.102,54.88 DD9.2@52.34,54.88 DD9.2@52.356,54.864
NetD1_1: D1.1 D2.13 D6.12 D14.35 D20.35 DD9.3 | length 305.8
  Top Layer w0.305: D2.13@10.16,87.63 12.7,87.63 13.97,86.36 v1(20.32,86.36) 20.32,84.582 19.304,83.566 19.304,79.756 20.32,78.74 20.32,61.214 22.86,58.674 26.543,58.674 27.797,57.42 D1.1@29.48,57.42 30.718,57.42 32.004,56.134 40.132,56.134 42.926,58.928 48.006,58.928 v1(49.276,57.658) ; v1(19.812,90.678) 19.812,91.948 17.272,94.488 17.272,112.573 16.053,113.792 16.053,124.206 17.831,125.984 18.968,125.984 19.311,126.327 27.933,126.327 28.53,125.73 31.75,125.73 v1(33.02,124.46) ; v1(73.152,117.856) 73.66,118.364 87.63,118.364 87.67,118.324 93.94,118.324 v1(94.488,118.872) ; v1(114.3,110.998) 115.481,112.179 161.709,112.179 162.56,113.03 162.56,115.57 162.306,115.824 160.274,115.824 D14.35@158.75,114.3
  Bottom Layer w0.305: v1(19.812,90.678) 20.32,90.17 v1(20.32,86.36) 28.956,86.36 32.766,90.17 D6.12@35.56,90.17 ; v1(33.02,124.46) 38.1,119.38 57.658,119.38 60.452,116.586 60.452,113.538 61.468,112.522 73.152,112.522 73.66,113.03 73.66,117.348 v1(73.152,117.856) ; v1(49.276,57.658) 50.038,56.896 50.038,54.102 51.8,52.34 DD9.3@52.34,52.34 ; v1(94.488,118.872) 97.79,115.57 D20.35@97.79,114.3 100.076,112.014 111.76,112.014 112.776,110.998 v1(114.3,110.998)
NetD1_3: D1.3 R3.2 | length 6.1
  Bottom Layer w0.305: R3.2@24.4,54.88 26.146,54.88 28.702,52.324 29.464,52.324 D1.3@29.48,52.34
NetD1_4: D1.4 D2.6 D6.23 | length 159.7
  Top Layer w0.305: v1(10.16,52.07) 11.43,50.8 28.48,50.8 D1.4@29.48,49.8 ; v1(10.16,55.118) 8.636,55.118 7.366,56.388 7.366,104.8 7.976,105.41 D2.6@10.16,105.41 12.7,105.41 15.24,102.87 v1@15.24,93.726
  Bottom Layer w0.305: v1(10.16,52.07) v1(10.16,55.118) ; v1(15.24,93.98) 15.24,92.71 14.732,92.202 14.732,72.39 20.269,66.853 43.688,66.853 45.72,68.885 45.72,73.66 46.99,74.93 D6.23@50.8,74.93
NetD1_5: D1.5 D6.19 | length 31
  Top Layer w0.305: v1@32.766,69.088 33.528,68.326 33.528,57.912 v1(33.02,57.404)
  Bottom Layer w0.305: D1.5@29.48,47.26 32.02,47.26 32.258,47.498 32.258,56.642 v1(33.02,57.404) v1@33.02,57.912 ; v1@32.766,69.088 32.766,70.866 34.29,72.39 D6.19@35.56,72.39
  other v1: 32.766,69.596
NetD1_6: D1.6 D2.12 | length 60.6
  Top Layer w0.381: v1(13.208,66.548) 13.208,60.706 14.986,58.928 v1(15.24,58.928)
  Bottom Layer w0.381: D2.12@10.16,90.17 11.938,90.17 13.208,88.9 v1(13.208,66.548) ; v1(15.24,58.928) 15.24,53.34 20.32,53.34 22.86,50.8 25.4,50.8 25.908,50.292 25.908,45.72 26.908,44.72 D1.6@29.48,44.72
NetD1_7: D1.7
NetD1_10: D1.10 D6.15 | length 53.7
  Top Layer w0.305: v1(29.718,69.596) 31.496,67.818 v1(31.496,59.944)
  Bottom Layer w0.305: v1(29.718,69.596) 29.718,71.882 31.496,73.66 37.084,73.66 37.592,74.168 37.592,80.518 D6.15@35.56,82.55 ; v1(31.496,59.944) 31.75,59.69 34.036,59.69 34.544,59.182 34.544,55.626 33.02,54.102 33.02,45.72 36.56,42.18 D1.10@37.1,42.18
NetD1_11: D1.11 D6.22 | length 42.7
  Bottom Layer w0.305: D1.11@37.1,44.72 35.576,44.72 35.56,44.704 34.036,46.228 34.036,50.038 35.052,51.054 38.608,51.054 40.118,52.564 40.118,57.136 43.434,60.452 45.974,60.452 52.832,67.31 52.832,71.374 51.816,72.39 D6.22@50.8,72.39
NetD1_12: D1.12 D3.14 D16.8 D16.9 | length 171.7
  Top Layer w0.305: D16.9@21.86,15.51 20.32,17.05 20.32,26.162 21.082,26.924 23.114,26.924 23.622,27.432 23.622,32.258 27.178,35.814 v1(40.64,35.814) 40.894,36.068 53.848,36.068 v1(54.61,36.83) ; v1@57.404,36.83 57.455,36.881 108.001,36.881 109.271,38.151 129.743,38.151 v1(130.81,37.084) v1@131.064,36.83 ; D3.14@131.08,57.42 131.096,57.404 133.096,57.404 134.366,56.134 v1(134.366,51.562)
  Bottom Layer w0.254: D16.8@21.86,12.97 D16.9@21.86,15.51
  Bottom Layer w0.305: D1.12@37.1,47.26 37.116,47.244 38.862,47.244 40.64,45.466 v1(40.64,35.814) ; v1(54.61,36.83) v1(57.912,36.83) ; v1(130.81,37.084) 133.096,39.37 133.096,50.292 v1(134.366,51.562)
NetD1_13: D1.13
NetD1_14: D1.14 Z1.2 | length 7.8
  Top Layer w0.305: D1.14@37.1,52.34 44.62,52.34 Z1.2@44.72,52.44
  Bottom Layer w0.305: Z1.2@44.62,52.34 Z1.2@44.72,52.44
NetD1_15: D1.15 Z1.1 | length 8.6
  Top Layer w0.305: D1.15@37.1,54.88 41.164,54.88 43.604,57.32 Z1.1@44.72,57.32
NetD2_1: D2.1 DD4.2 R4.1 | length 204.5
  Top Layer w0.305: D2.1@10.16,118.11 6.35,118.11 3.048,114.808 3.048,53.086 5.08,51.054 5.08,47.752 5.588,47.244 7.112,47.244 8.89,49.022 16.002,49.022 18.085,46.939 24.689,46.939 26.924,44.704 26.924,41.91 27.94,40.894 40.64,40.894 41.402,41.656 48.006,41.656 49.784,39.878 54.102,39.878 v1(54.61,39.37) ; v1(57.912,39.37) 59.182,38.1 v1(70.358,38.1) ; v1(78.74,39.878) 92.964,39.878 93.98,40.894 104.394,40.894 107.188,43.688 107.188,55.118 R4.1@106.426,55.88
  Bottom Layer w0.305: v1(54.61,39.37) v1(57.912,39.37) ; v1(70.358,38.1) 76.962,38.1 v1(78.74,39.878) ; R4.1@106.426,55.88 107.426,54.88 DD4.2@109.49,54.88
NetD2_2: D2.2 D5.13 D6.18 D14.36 D20.36 | length 327.1
  Top Layer w0.305: D2.2@10.16,115.57 12.7,115.57 12.954,115.316 12.954,112.522 16.51,108.966 v1(16.51,92.71) ; D6.18@35.56,74.93 v1(44.196,74.93) ; v1(106.426,58.42) 108.966,60.96 108.966,64.516 111.252,66.802 111.252,74.168 v1(109.22,76.2)
  Top Layer w0.381: 12.7,115.57 12.7,126.492 13.97,127.762 18.321,127.762 18.601,128.041 28.643,128.041 28.923,127.762 34.544,127.762 36.068,126.238 89.154,126.238 v1(89.662,125.73) v1@89.789,125.603 ; v1(113.284,112.776) 160.02,112.776 161.29,114.046 D14.36@161.29,114.3
  Bottom Layer w0.305: v1(16.51,92.71) 16.51,79.756 17.526,78.74 17.526,77.47 18.237,76.759 22.403,76.759 24.384,78.74 31.75,78.74 D6.18@35.56,74.93 ; D5.13@89.17,54.88 89.186,54.864 90.17,54.864 94.234,58.928 99.06,58.928 101.854,56.134 104.14,56.134 v1(106.426,58.42) ; v1(109.22,76.2) 120.599,87.579 120.599,106.731 114.554,112.776 v1(113.284,112.776)
  Bottom Layer w0.381: v1(89.662,125.73) 90.424,125.73 100.33,115.824 D20.36@100.33,114.3 101.854,112.776 v1(113.284,112.776)
NetD2_3: D2.3
NetD2_4: D2.4 D5.2 R5.2 | length 139.6
  Top Layer w0.305: D2.4@10.16,110.49 8.382,110.49 6.604,108.712 6.604,54.864 7.874,53.594 31.75,53.594 34.29,51.054 38.354,51.054 40.894,48.514 54.61,48.514 57.15,51.054 71.374,51.054 73.914,53.594 76.708,53.594 78.232,55.118 R5.2@78.232,55.88
  Bottom Layer w0.305: R5.2@78.232,55.88 79.232,54.88 D5.2@81.55,54.88
NetD2_5: D2.5
NetD2_7: D2.7 D6.21 | length 74.7
  Top Layer w0.305: D2.7@10.16,102.87 12.7,102.87 13.97,101.6 v1(13.97,95.25)
  Bottom Layer w0.305: v1(13.97,95.25) 13.97,71.882 19.558,66.294 47.244,66.294 D6.21@50.8,69.85
NetD2_8: D2.8 D7.11 | length 106.3
  Top Layer w0.305: D2.8@10.16,100.33 11.176,100.33 12.7,98.806 12.7,94.742 18.542,88.9 21.082,88.9 21.935,88.047 21.935,83.911 20.828,82.804 20.828,80.264 21.59,79.502 21.59,73.914 24.384,71.12 27.178,71.12 27.686,71.628 30.988,71.628 33.02,73.66 71.12,73.66 73.66,76.2 76.962,76.2 80.772,72.39 D7.11@88.9,72.39
NetD2_9: D2.9 D7.13 | length 127.1
  Top Layer w0.305: D2.9@10.16,97.79 12.141,95.809 12.141,94.285 18.288,88.138 20.574,88.138 21.376,87.336 21.376,85.922 21.082,85.628 21.082,84.074 20.066,83.058 20.066,80.01 21.031,79.045 21.031,69.139 21.844,68.326 26.924,68.326 27.686,69.088 27.686,70.358 28.194,70.866 31.242,70.866 31.496,71.12 40.894,71.12 41.91,72.136 46.482,72.136 47.498,71.12 v1(58.166,71.12)
  Bottom Layer w0.305: v1(58.166,71.12) 64.77,71.12 68.58,67.31 83.058,67.31 86.868,71.12 89.916,71.12 90.932,70.104 96.042,70.104 98.023,72.085 101.346,72.085 103.581,69.85 D7.13@104.14,69.85
NetD2_10: D2.10 D6.13 | length 39.8
  Bottom Layer w0.305: D2.10@10.16,95.25 11.684,95.25 12.954,96.52 14.732,96.52 17.78,93.472 17.78,86.36 17.272,85.852 17.272,83.82 18.034,83.058 19.812,83.058 20.574,83.82 28.956,83.82 32.766,87.63 D6.13@35.56,87.63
